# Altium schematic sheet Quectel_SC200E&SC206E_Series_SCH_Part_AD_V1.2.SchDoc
size A1
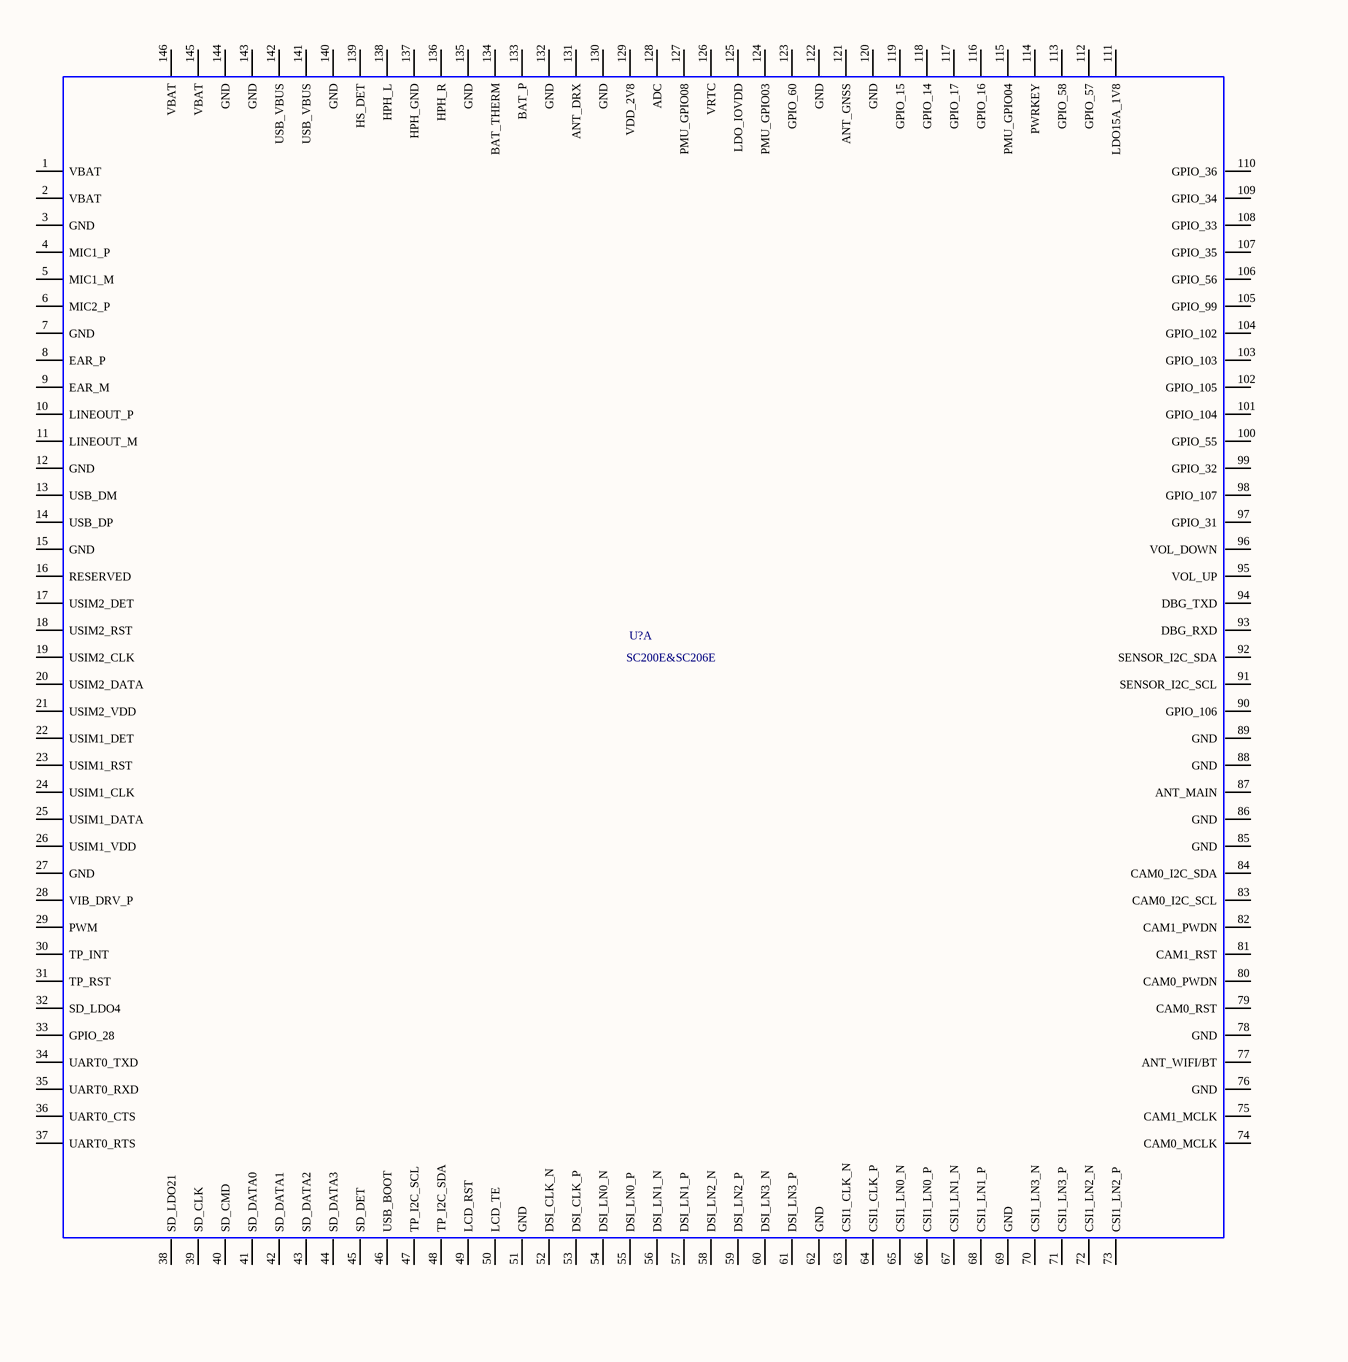
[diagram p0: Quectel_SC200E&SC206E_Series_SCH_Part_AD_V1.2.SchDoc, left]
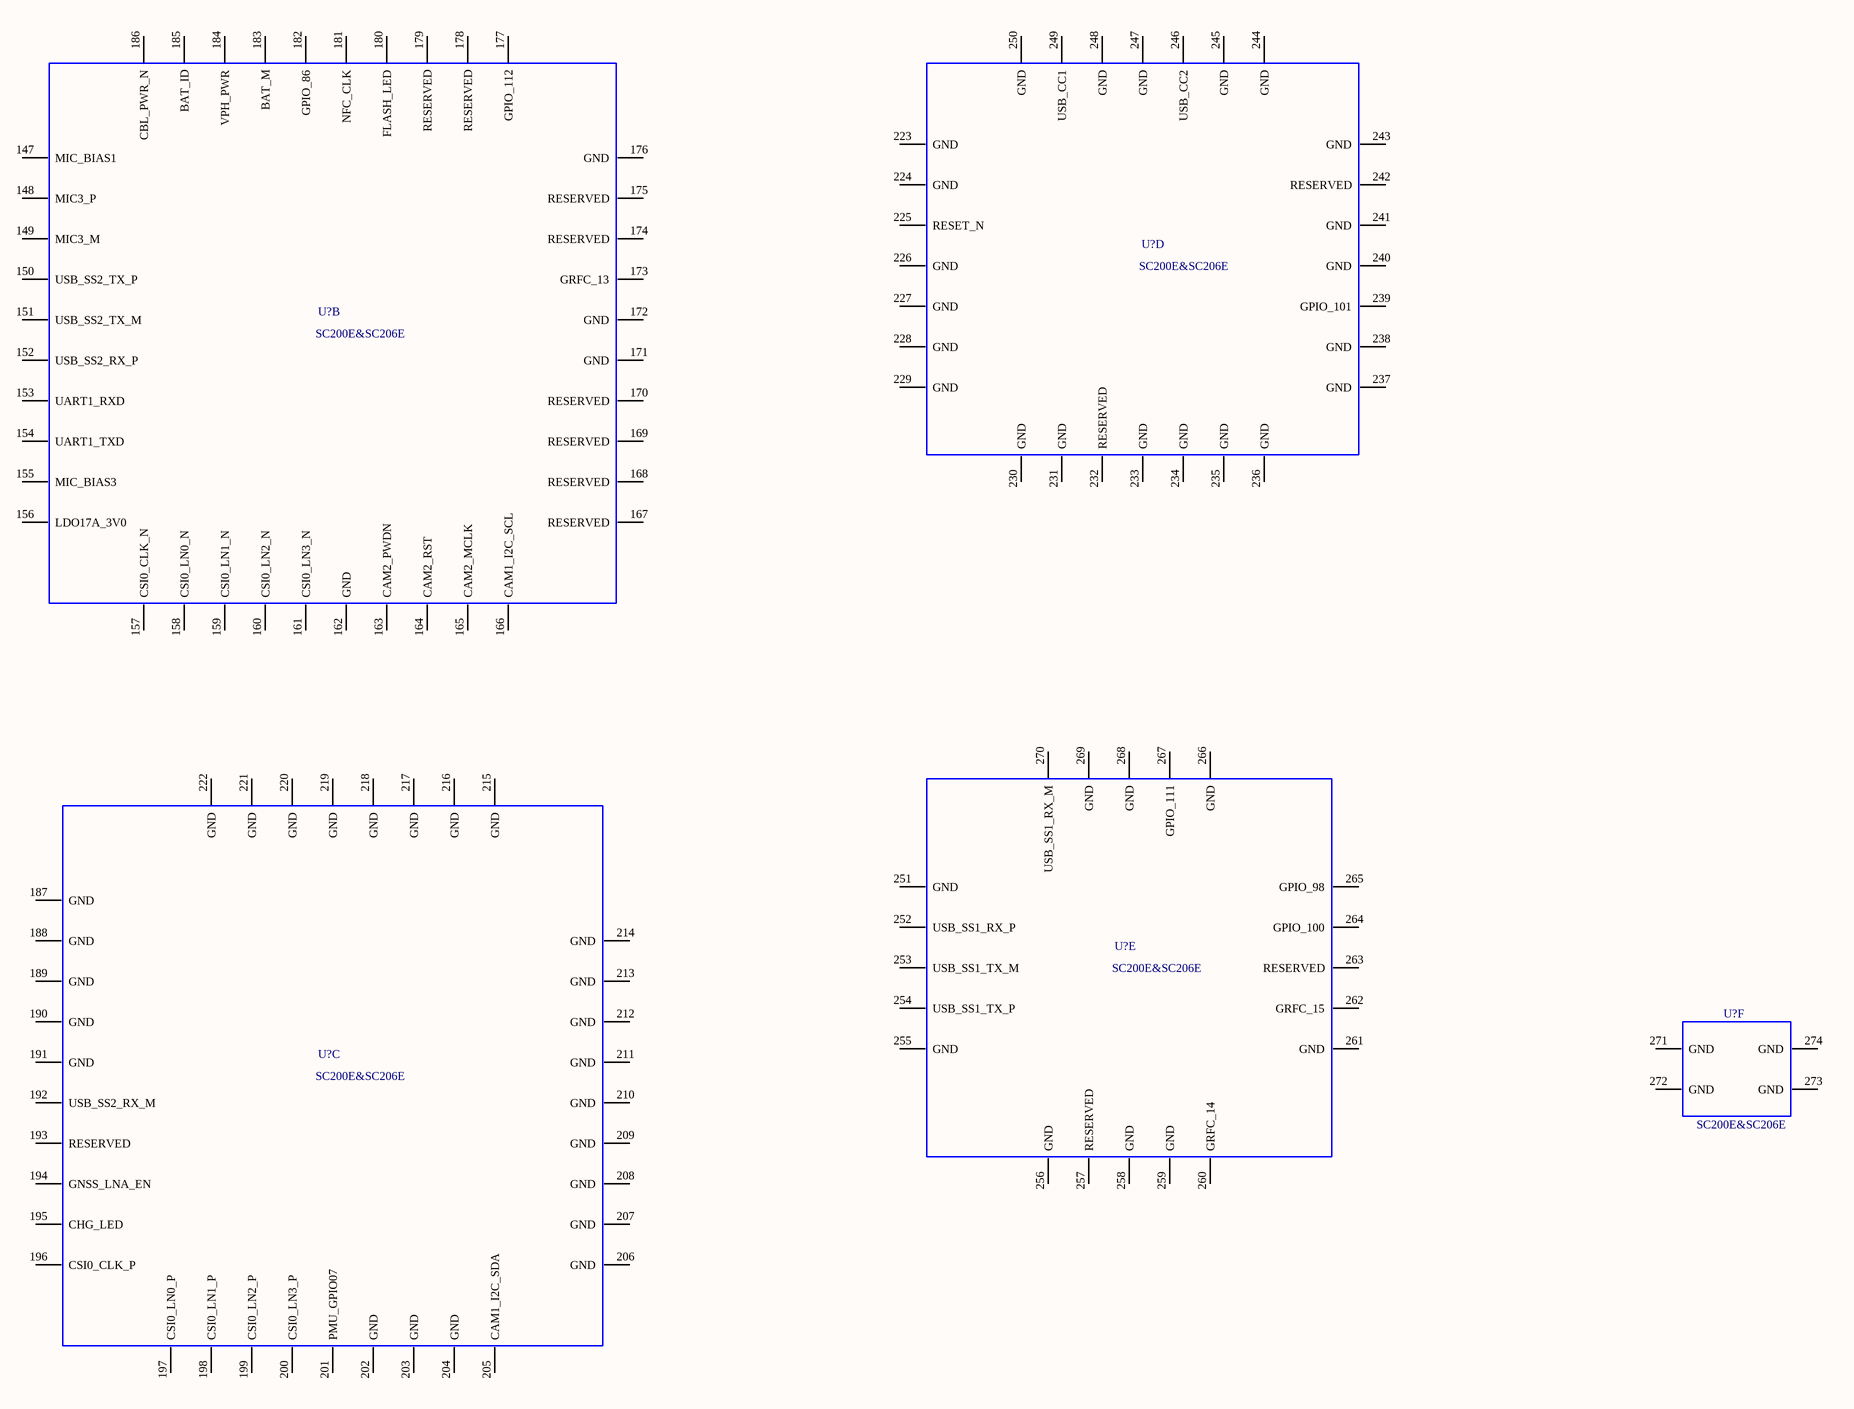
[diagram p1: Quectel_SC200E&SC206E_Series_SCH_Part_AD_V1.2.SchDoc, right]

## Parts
(Parts that share a designator on the sheet are numbered #1, #2 ... from top to bottom, then left to right.)
U?#1  SC200E&SC206E  (part D of 6)
U?#2  SC200E&SC206E  (part B of 6)
U?#3  SC200E&SC206E  (part A of 6)
U?#4  SC200E&SC206E  (part E of 6)
U?#5  SC200E&SC206E  (part F of 6)
U?#6  SC200E&SC206E  (part C of 6)

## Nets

Not connected (* = marked no-connect by the designer): U?#1 223(GND) 224(GND) 225(RESET_N) 226(GND) 227(GND) 228(GND) 229(GND) 230(GND) 231(GND) 232(RESERVED) 233(GND) 234(GND) 235(GND) 236(GND) 237(GND) 238(GND) 239(GPIO_101) 240(GND) 241(GND) 242(RESERVED) 243(GND) 244(GND) 245(GND) 246(USB_CC2) 247(GND) 248(GND) 249(USB_CC1) 250(GND); U?#2 147(MIC_BIAS1) 148(MIC3_P) 149(MIC3_M) 150(USB_SS2_TX_P) 151(USB_SS2_TX_M) 152(USB_SS2_RX_P) 153(UART1_RXD) 154(UART1_TXD) 155(MIC_BIAS3) 156(LDO17A_3V0) 157(CSI0_CLK_N) 158(CSI0_LN0_N) 159(CSI0_LN1_N) 160(CSI0_LN2_N) 161(CSI0_LN3_N) 162(GND) 163(CAM2_PWDN) 164(CAM2_RST) 165(CAM2_MCLK) 166(CAM1_I2C_SCL) 167(RESERVED) 168(RESERVED) 169(RESERVED) 170(RESERVED) 171(GND) 172(GND) 173(GRFC_13) 174(RESERVED) 175(RESERVED) 176(GND) 177(GPIO_112) 178(RESERVED) 179(RESERVED) 180(FLASH_LED) 181(NFC_CLK) 182(GPIO_86) 183(BAT_M) 184(VPH_PWR) 185(BAT_ID) 186(CBL_PWR_N); U?#3 1(VBAT) 2(VBAT) 3(GND) 4(MIC1_P) 5(MIC1_M) 6(MIC2_P) 7(GND) 8(EAR_P) 9(EAR_M) 10(LINEOUT_P) 11(LINEOUT_M) 12(GND) 13(USB_DM) 14(USB_DP) 15(GND) 16(RESERVED) 17(USIM2_DET) 18(USIM2_RST) 19(USIM2_CLK) 20(USIM2_DATA) 21(USIM2_VDD) 22(USIM1_DET) 23(USIM1_RST) 24(USIM1_CLK) 25(USIM1_DATA) 26(USIM1_VDD) 27(GND) 28(VIB_DRV_P) 29(PWM) 30(TP_INT) 31(TP_RST) 32(SD_LDO4) 33(GPIO_28) 34(UART0_TXD) 35(UART0_RXD) 36(UART0_CTS) 37(UART0_RTS) 38(SD_LDO21) 39(SD_CLK) 40(SD_CMD) 41(SD_DATA0) 42(SD_DATA1) 43(SD_DATA2) 44(SD_DATA3) 45(SD_DET) 46(USB_BOOT) 47(TP_I2C_SCL) 48(TP_I2C_SDA) 49(LCD_RST) 50(LCD_TE) 51(GND) 52(DSI_CLK_N) 53(DSI_CLK_P) 54(DSI_LN0_N) 55(DSI_LN0_P) 56(DSI_LN1_N) 57(DSI_LN1_P) 58(DSI_LN2_N) 59(DSI_LN2_P) 60(DSI_LN3_N) 61(DSI_LN3_P) 62(GND) 63(CSI1_CLK_N) 64(CSI1_CLK_P) 65(CSI1_LN0_N) 66(CSI1_LN0_P) 67(CSI1_LN1_N) 68(CSI1_LN1_P) 69(GND) 70(CSI1_LN3_N) 71(CSI1_LN3_P) 72(CSI1_LN2_N) 73(CSI1_LN2_P) 74(CAM0_MCLK) 75(CAM1_MCLK) 76(GND) 77(ANT_WIFI/BT) 78(GND) 79(CAM0_RST) 80(CAM0_PWDN) 81(CAM1_RST) 82(CAM1_PWDN) 83(CAM0_I2C_SCL) 84(CAM0_I2C_SDA) 85(GND) 86(GND) 87(ANT_MAIN) 88(GND) 89(GND) 90(GPIO_106) 91(SENSOR_I2C_SCL) 92(SENSOR_I2C_SDA) 93(DBG_RXD) 94(DBG_TXD) 95(VOL_UP) 96(VOL_DOWN) 97(GPIO_31) 98(GPIO_107) 99(GPIO_32) 100(GPIO_55) 101(GPIO_104) 102(GPIO_105) 103(GPIO_103) 104(GPIO_102) 105(GPIO_99) 106(GPIO_56) 107(GPIO_35) 108(GPIO_33) 109(GPIO_34) 110(GPIO_36) 111(LDO15A_1V8) 112(GPIO_57) 113(GPIO_58) 114(PWRKEY) 115(PMU_GPIO04) 116(GPIO_16) 117(GPIO_17) 118(GPIO_14) 119(GPIO_15) 120(GND) 121(ANT_GNSS) 122(GND) 123(GPIO_60) 124(PMU_GPIO03) 125(LDO_IOVDD) 126(VRTC) 127(PMU_GPIO08) 128(ADC) 129(VDD_2V8) 130(GND) 131(ANT_DRX) 132(GND) 133(BAT_P) 134(BAT_THERM) 135(GND) 136(HPH_R) 137(HPH_GND) 138(HPH_L) 139(HS_DET) 140(GND) 141(USB_VBUS) 142(USB_VBUS) 143(GND) 144(GND) 145(VBAT) 146(VBAT); U?#4 251(GND) 252(USB_SS1_RX_P) 253(USB_SS1_TX_M) 254(USB_SS1_TX_P) 255(GND) 256(GND) 257(RESERVED) 258(GND) 259(GND) 260(GRFC_14) 261(GND) 262(GRFC_15) 263(RESERVED) 264(GPIO_100) 265(GPIO_98) 266(GND) 267(GPIO_111) 268(GND) 269(GND) 270(USB_SS1_RX_M); U?#5 271(GND) 272(GND) 273(GND) 274(GND); U?#6 187(GND) 188(GND) 189(GND) 190(GND) 191(GND) 192(USB_SS2_RX_M) 193(RESERVED) 194(GNSS_LNA_EN) 195(CHG_LED) 196(CSI0_CLK_P) 197(CSI0_LN0_P) 198(CSI0_LN1_P) 199(CSI0_LN2_P) 200(CSI0_LN3_P) 201(PMU_GPIO07) 202(GND) 203(GND) 204(GND) 205(CAM1_I2C_SDA) 206(GND) 207(GND) 208(GND) 209(GND) 210(GND) 211(GND) 212(GND) 213(GND) 214(GND) 215(GND) 216(GND) 217(GND) 218(GND) 219(GND) 220(GND) 221(GND) 222(GND)

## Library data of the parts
U?#1-U?#6 = SC200E: SC200E Smart Module RO; Manufacturer: QUECTEL; Geometry.Height: 2.85mm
